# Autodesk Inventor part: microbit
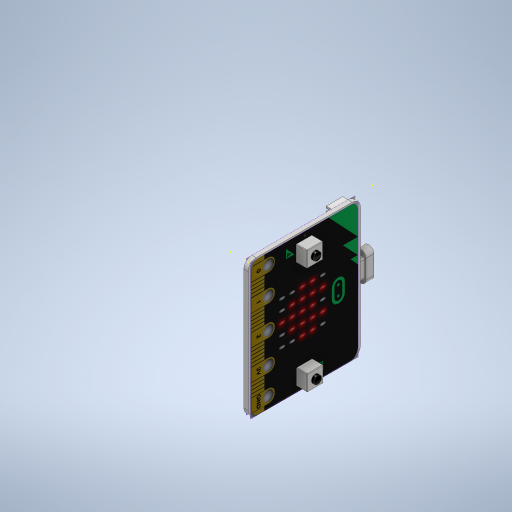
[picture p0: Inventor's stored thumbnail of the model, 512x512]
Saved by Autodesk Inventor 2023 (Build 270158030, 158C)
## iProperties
Part Number: microbit
Material: Générique
Document SubType Name: Modeling
Designer: Buhl
Density: 1 g/cm^3
Appearance: Par défaut
Author: Buhl
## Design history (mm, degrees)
sketch "Esquisse1"
  geometry: L1 (3, 0)-(39, 0); L2 (42, -3)-(42, -48); L3 (39, -51)-(3, -51); L4 (0, -48)-(0, -3); A1 r 2 centre (40, -49) between (40, -51) and (42, -49); A2 r 2 centre (40, -2) between (42, -2) and (40, 0); A3 r 3 centre (39, -48) between (39, -51) and (42, -48); A4 r 3 centre (39, -3) between (42, -3) and (39, 0); A5 r 3 centre (3, -3) between (3, 0) and (0, -3); A6 r 3 centre (3, -48) between (0, -48) and (3, -51); 4 further points
  constraints: 12 point on circle, 12 point on line, 12 tangent, 8 end point, 6 centre point, 4 equal radius, 2 parallel, 1 horizontal, 1 perpendicular
  dimensions: "d0" = 42 distance of point (42, -51) point (0, -51); "d1" = 51 distance of point (42, 0) point (42, -51); "d2" = 2 radius of A1 (derived); "d3" = 3 radius of A3
extrude "Extrusion1" new body sketch "Esquisse1" distance "d4" = 1.6; taper "d5" = 0 deg
sketch "Esquisse2"
  geometry: L1 (0.566, 41.203)-(51.277, 41.203); L2 (51.277, 41.203)-(51.277, 0.803); L3 (51.277, 0.803)-(0.566, 0.803); L4 (0.566, 0.803)-(0.566, 41.203); 1 further point; 1 other entity
  constraints: 2 other
  node "Image1"
sketch "Esquisse3"
  geometry: L1 (-50.817, 41.619)-(-0.018, 41.619); L2 (-0.018, 41.619)-(-0.018, 0.936); L3 (-0.018, 0.936)-(-50.817, 0.936); L4 (-50.817, 0.936)-(-50.817, 41.619); 1 further point; 1 other entity
  constraints: 2 other
  node "Image2"
sketch "Esquisse4"
  geometry: L1 (3.141, 24.01)-(9.141, 24.01); L2 (9.141, 24.01)-(9.141, 18.01); L3 (9.141, 18.01)-(3.141, 18.01); L4 (3.141, 18.01)-(3.141, 24.01); 1 further point
  constraints: 8 end point, 2 parallel, 1 horizontal, 1 perpendicular
  dimensions: "d40" = 6 distance of L2.end L3.end; "d41" = 6 distance of L1.end L2.end
extrude "Extrusion2" join sketch "Esquisse4" distance "d42" = 4; taper "d43" = 0 deg
fillet "Congé1" dims "d46" = 0.2
fillet "Congé2" dims "d47" = 0.2
sketch "Esquisse5"
  geometry: L1 (3.341, 18.21)-(3.341, 23.81) reference; L2 (8.941, 23.81)-(8.941, 18.21) reference; L3 (3.341, 23.81)-(8.941, 23.81) reference; C1 r 1.5 at (6.141, 21.01); 1 further point
  constraints: 1 centre point
  dimensions: "d48" = 3 diameter of C1
extrude "Extrusion3" join sketch "Esquisse5" distance "d49" = 1; taper "d50" = 0 deg
fillet "Congé3" dims "d51" = 0.1
sketch "Esquisse6"
  geometry: L1 (43.242, 24.154)-(49.242, 24.154); L2 (49.242, 24.154)-(49.242, 18.154); L3 (49.242, 18.154)-(43.242, 18.154); L4 (43.242, 18.154)-(43.242, 24.154); 1 further point
  constraints: 8 end point, 2 parallel, 1 horizontal, 1 perpendicular
  dimensions: "d52" = 6 distance of L2.end L3.end; "d53" = 6 distance of L1.end L2.end
extrude "Extrusion4" join sketch "Esquisse6" distance "d54" = 4; taper "d55" = 0 deg
fillet "Congé4" dims "d56" = 0.2
fillet "Congé5" dims "d57" = 0.2
sketch "Esquisse7"
  geometry: L1 (49.042, 23.954)-(49.042, 18.354) reference; L2 (49.042, 23.954)-(49.242, 23.954) reference; L3 (43.442, 18.354)-(43.442, 23.954) reference; C1 r 1.5 at (46.242, 21.154); A1 r 0.2 centre (43.442, 23.954) between (43.442, 24.154) and (43.242, 23.954) reference; 1 further point
  constraints: 1 centre point
  dimensions: "d58" = 3 diameter of C1
extrude "Extrusion5" join sketch "Esquisse7" distance "d59" = 1; taper "d60" = 0 deg
fillet "Congé6" dims "d61" = 0.1
sketch "Esquisse8"
  geometry: L1 (-12.86, 35.794)-(-18.86, 35.794); L2 (-18.86, 35.794)-(-18.86, 41.794); L3 (-18.86, 41.794)-(-12.86, 41.794); L4 (-12.86, 41.794)-(-12.86, 35.794); L5 (-12.86, 35.794)-(-18.86, 41.794); L6 (-18.86, 35.794)-(-12.86, 41.794); 2 further points
  constraints: 12 end point, 2 midpoint, 2 parallel, 1 horizontal, 1 perpendicular
  dimensions: "d62" = 6 distance of L2.end L3.end; "d63" = 6 distance of L1.end L2.end
extrude "Extrusion6" join sketch "Esquisse8" distance "d64" = 4; taper "d65" = 0 deg
fillet "Congé7" dims "d66" = 0.2
fillet "Congé8" dims "d67" = 0.2
sketch "Esquisse9"
  geometry: L1 (-18.66, 35.994)-(-18.66, 41.594) reference; L2 (-13.06, 35.994)-(-18.66, 35.994) reference; L3 (-18.66, 41.594)-(-13.06, 41.594) reference; C1 r 1.5 at (-15.86, 38.794); 1 further point
  constraints: 1 centre point
  dimensions: "d68" = 3 diameter of C1
extrude "Extrusion7" join sketch "Esquisse9" distance "d69" = 1; taper "d70" = 0 deg
fillet "Congé9" dims "d71" = 0.1
sketch "Esquisse10"
  geometry: L1 (-28.891, 38.196)-(-21.891, 38.196); L2 (-21.891, 38.196)-(-21.891, 45.196); L3 (-21.891, 45.196)-(-28.891, 45.196); L4 (-28.891, 45.196)-(-28.891, 38.196); 1 further point
  constraints: 8 end point, 2 parallel, 1 horizontal, 1 perpendicular
  dimensions: "d72" = 7 distance of L3.end L2.end; "d73" = 7 distance of L2.end L1.end
extrude "Extrusion8" join sketch "Esquisse10" distance "d74" = 3; taper "d75" = 0 deg
sketch "Esquisse12"
  geometry: L1 (0, 26.109)-(0, 7) reference; L2 (-3, 0)-(-3, 7) reference; L3 (0, 0)-(-3, 0) reference; L4 (-1.5, 0)-(-1.5, 7); L5 (0, 7)-(-3, 7) reference; L6 (0.5, 0)-(0.5, 7); L7 (-3.5, 7)-(-3.5, 0); A1 r 2 centre (-1.5, 0) between (-3.5, 0) and (0.5, 0); A2 r 2 centre (-1.5, 7) between (0.5, 7) and (-3.5, 7); 2 further points
  constraints: 8 end point, 4 point on circle, 4 tangent, 2 centre point, 2 midpoint, 1 parallel
extrude "Extrusion10" join sketch "Esquisse12" distance "d80" = 3; taper "d81" = 0 deg
fillet "Congé10" dims "d82" = 0.5
sketch "Esquisse13"
  geometry: 1 further point
sketch "Esquisse14"
  geometry: L1 (-43.375, 33.249)-(-37.775, 33.249); L2 (-37.775, 33.249)-(-37.775, 27.649); L3 (-37.775, 27.649)-(-43.375, 27.649); L4 (-43.375, 27.649)-(-43.375, 33.249); 1 further point
  constraints: 8 end point, 2 parallel, 1 horizontal, 1 perpendicular
  dimensions: "d83" = 5.6 distance of L2.end L3.end; "d84" = 5.6 distance of L1.end L2.end
extrude "Extrusion11" join sketch "Esquisse14" distance "d85" = 1; taper "d86" = 0 deg
sketch "Esquisse15"
  geometry: L1 (-13.681, 30.417)-(-9.181, 30.417); L2 (-9.181, 30.417)-(-9.181, 25.917); L3 (-9.181, 25.917)-(-13.681, 25.917); L4 (-13.681, 25.917)-(-13.681, 30.417); 1 further point
  constraints: 8 end point, 2 parallel, 1 horizontal, 1 perpendicular
  dimensions: "d87" = 4.5 distance of L2.end L3.end; "d88" = 4.5 distance of L1.end L2.end
extrude "Extrusion12" join sketch "Esquisse15" distance "d89" = 1; taper "d90" = 0 deg
sketch "Esquisse16"
  geometry: L1 (-47.39, 18.329)-(-45.19, 18.329); L2 (-45.19, 18.329)-(-45.19, 16.129); L3 (-45.19, 16.129)-(-47.39, 16.129); L4 (-47.39, 16.129)-(-47.39, 18.329); 1 further point
  constraints: 8 end point, 2 parallel, 1 horizontal, 1 perpendicular
  dimensions: "d91" = 2.2 distance of L2.end L3.end; "d92" = 2.2 distance of L1.end L2.end
extrude "Extrusion13" join sketch "Esquisse16" distance "d93" = 1; taper "d94" = 0 deg
sketch "Esquisse17"
  geometry: L1 (-11.005, 35.782)-(-3.005, 35.782); L2 (-3.005, 35.782)-(-3.005, 41.982); L3 (-3.005, 41.982)-(-11.005, 41.982); L4 (-11.005, 41.982)-(-11.005, 35.782); 1 further point
  constraints: 8 end point, 2 parallel, 1 horizontal, 1 perpendicular
  dimensions: "d95" = 8 distance of L3.end L2.end; "d96" = 6.2 distance of L2.end L1.end
extrude "Extrusion14" join sketch "Esquisse17" distance "d97" = 5; taper "d98" = 0 deg
sketch "Esquisse18"
  geometry: L1 (-0.75, 0.75)-(-4.25, 0.75); L2 (-4.25, 0.75)-(-4.25, 7.25); L3 (-4.25, 7.25)-(-0.75, 7.25); L4 (-0.75, 7.25)-(-0.75, 0.75); 1 further point
  constraints: 8 end point, 2 parallel, 1 horizontal, 1 perpendicular
  dimensions: "d99" = 3.5 distance of L2.end L3.end; "d100" = 6.5 distance of L1.end L2.end
extrude "Extrusion15" cut sketch "Esquisse18" distance "d101" = 5; taper "d102" = 0 deg
sketch "Esquisse19"
  geometry: L1 (-3.644, 34.795)-(-4.644, 34.795); L2 (-4.644, 34.795)-(-4.644, 38.795); L3 (-4.644, 38.795)-(-3.644, 38.795) reference; L4 (-3.644, 38.795)-(-3.644, 34.795); 1 further point
  constraints: 8 end point, 2 horizontal, 2 parallel, 1 perpendicular
  dimensions: "d103" = 1 distance of L2.end L3.end; "d104" = 4 distance of L1.end L2.end
extrude "Extrusion16" cut sketch "Esquisse19" distance "d105" = 2; taper "d106" = 0 deg
sketch "Esquisse20"
  geometry: 1 further point
sketch "Esquisse21"
  geometry: L1 (-11.005, 35.782)-(-3.005, 35.782) reference; L2 (-10.249, 35.782)-(-9.249, 35.782); L3 (-9.249, 35.782)-(-9.249, 38.782); L4 (-9.249, 38.782)-(-10.249, 38.782); L5 (-10.249, 38.782)-(-10.249, 35.782); 2 further points
  constraints: 8 end point, 2 parallel, 1 horizontal, 1 perpendicular, 1 point on line
  dimensions: "d107" = 1 distance of L4.end L3.end; "d108" = 3 distance of L3.end L2.end
extrude "Extrusion17" cut sketch "Esquisse21" distance "d109" = 2; taper "d110" = 0 deg
sketch "Esquisse22"
  geometry: L1 (-13.681, 30.417)-(-9.181, 30.417) reference; L2 (-9.181, 25.917)-(-13.681, 25.917) reference; L3 (-13.681, 30.417)-(-9.181, 30.417); L4 (-9.181, 30.417)-(-9.181, 25.917); L5 (-9.181, 25.917)-(-13.681, 25.917); L6 (-13.681, 25.917)-(-13.681, 30.417); 3 further points
  constraints: 8 end point, 2 parallel, 1 horizontal, 1 perpendicular
extrude "Extrusion18" join sketch "Esquisse22" distance "d111" = 1; taper "d112" = 0 deg
node "Solide1"
